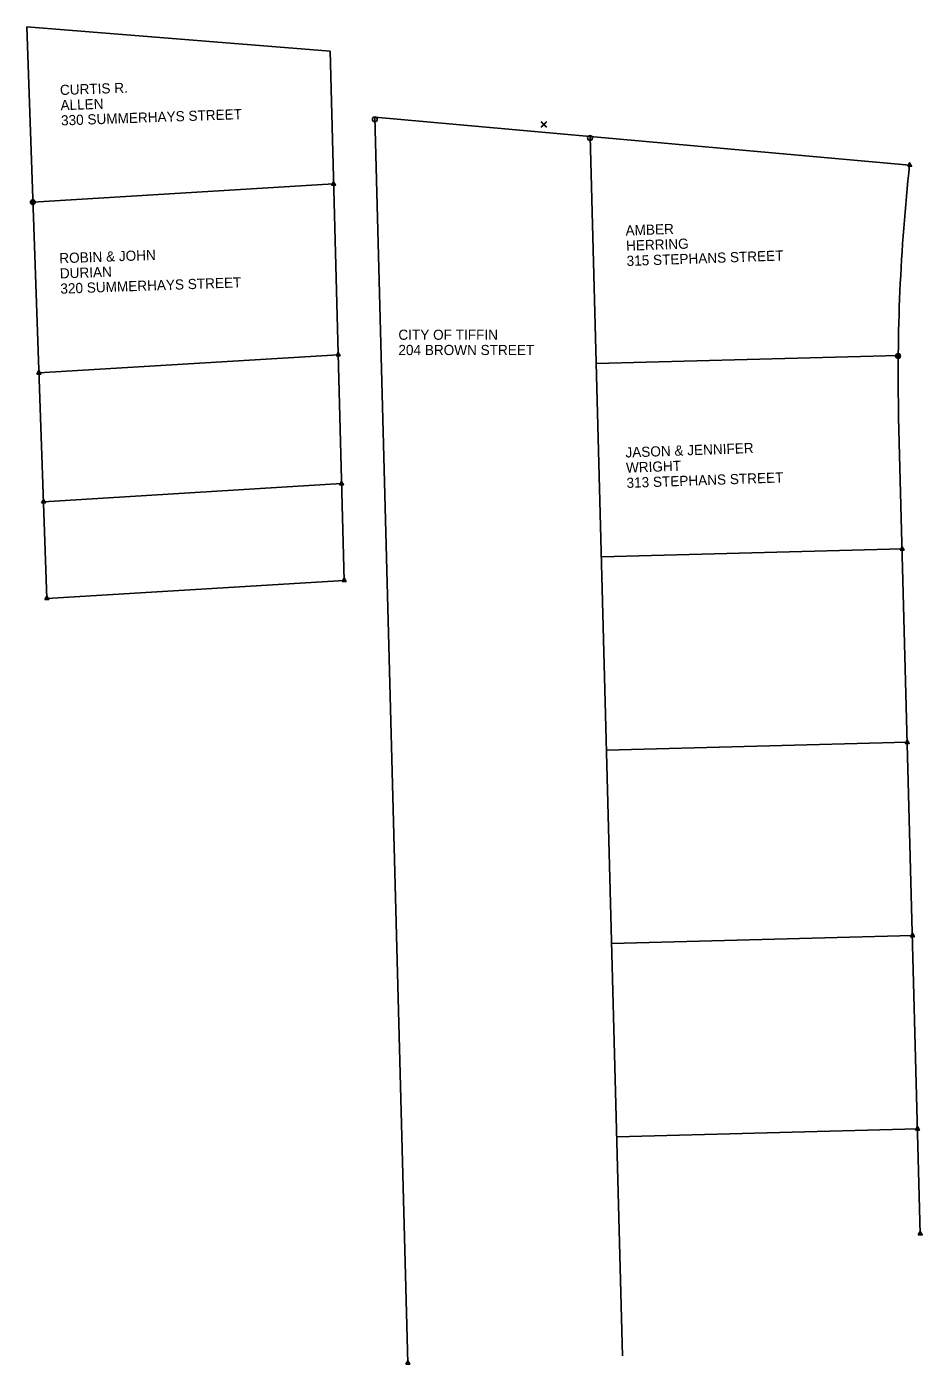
# Model space of a CAD drawing. Extents: x 20500076 to 20505422, y 7951999 to 7957351.
# Drawn here: x 20501309 to 20501726, y 7953265 to 7953888 of the extents above; entities that cross this region are included whole.
import ezdxf

# ---------------------------------------------------------------- set-up
doc = ezdxf.new("R2010")
doc.units = 0
for name, color, linetype in [('ControlPoints', 7, 'Continuous'), ('DisROW Existing', 7, 'Continuous'), ('DisROW Property Lines', 7, 'Continuous'), ('SurControl', 7, 'Continuous'), ('SurSectionCorner', 7, 'Continuous'), ('Text', 7, 'Continuous')]:
    doc.layers.add(name, color=color, linetype=linetype)

msp = doc.modelspace()

# ---------------------------------------------------------------- linework, layer by layer
at = {"layer": 'ControlPoints'}
msp.add_lwpolyline([(20501551.02, 7953843.51), (20501550.89, 7953843.64), (20501549.82, 7953842.53), (20501548.75, 7953843.64), (20501548.62, 7953843.51), (20501549.7, 7953842.4), (20501548.62, 7953841.29), (20501548.75, 7953841.16), (20501549.82, 7953842.27), (20501550.89, 7953841.16), (20501551.02, 7953841.29), (20501549.94, 7953842.4)], close=True, dxfattribs=at)
at = {"layer": 'DisROW Existing'}
for p, q in [((20501318.46, 7953621.8), (20501309.14, 7953887.86)), ((20501450.32, 7953876.56), (20501309.14, 7953887.86)), ((20501450.32, 7953876.56), (20501456.84, 7953630.2)), ((20501471.14, 7953845.77), (20501486.5, 7953265.88)), ((20501720.05, 7953823.49), (20501471.14, 7953845.77)), ((20501714.93, 7953705.96), (20501724.99, 7953326.1))]:
    msp.add_line(p, q, dxfattribs=at)
msp.add_arc((20502596.41, 7953726.45), 881.72, 173.68119, 181.33139, dxfattribs=at)
at = {"layer": 'DisROW Property Lines'}
for p, q in [((20501571.41, 7953836.8), (20501586.45, 7953269.21)), ((20501311.99, 7953806.19), (20501451.96, 7953814.69)), ((20501314.78, 7953726.77), (20501454.06, 7953735.22)), ((20501574.21, 7953731.06), (20501714.68, 7953734.78)), ((20501316.88, 7953666.79), (20501455.65, 7953675.21)), ((20501576.6, 7953641.09), (20501716.55, 7953644.8)), ((20501318.46, 7953621.8), (20501456.84, 7953630.2)), ((20501578.98, 7953551.12), (20501718.93, 7953554.83)), ((20501581.36, 7953461.15), (20501721.32, 7953464.86)), ((20501583.74, 7953371.19), (20501723.7, 7953374.89))]:
    msp.add_line(p, q, dxfattribs=at)
at = {"layer": 'SurControl'}
for centre in [(20501471.16, 7953844.78), (20501571.28, 7953836.09), (20501311.95, 7953806.22), (20501311.98, 7953806.19), (20501714.65, 7953734.63)]:
    msp.add_circle(centre, 1.12, dxfattribs=at)
at = {"layer": 'SurSectionCorner'}
for points in [[(20501719.13, 7953822.96), (20501720.96, 7953822.96), (20501720.05, 7953824.55)], [(20501451.04, 7953814.16), (20501452.87, 7953814.16), (20501451.96, 7953815.74)], [(20501311.09, 7953805.66), (20501312.92, 7953805.66), (20501312, 7953807.25)], [(20501453.15, 7953734.7), (20501454.97, 7953734.7), (20501454.06, 7953736.28)], [(20501713.82, 7953734.25), (20501715.65, 7953734.25), (20501714.73, 7953735.84)], [(20501313.87, 7953726.24), (20501315.7, 7953726.24), (20501314.78, 7953727.83)], [(20501454.74, 7953674.68), (20501456.56, 7953674.68), (20501455.65, 7953676.27)], [(20501315.97, 7953666.26), (20501317.8, 7953666.26), (20501316.88, 7953667.84)], [(20501715.64, 7953644.27), (20501717.46, 7953644.27), (20501716.55, 7953645.85)], [(20501455.93, 7953629.67), (20501457.76, 7953629.67), (20501456.84, 7953631.26)], [(20501317.54, 7953621.27), (20501319.37, 7953621.27), (20501318.46, 7953622.86)], [(20501718.02, 7953554.3), (20501719.85, 7953554.3), (20501718.93, 7953555.89)], [(20501720.4, 7953464.33), (20501722.23, 7953464.33), (20501721.32, 7953465.92)], [(20501722.78, 7953374.37), (20501724.61, 7953374.37), (20501723.7, 7953375.95)], [(20501724.08, 7953325.57), (20501725.91, 7953325.57), (20501724.99, 7953327.15)], [(20501485.59, 7953265.36), (20501487.42, 7953265.36), (20501486.5, 7953266.94)]]:
    msp.add_lwpolyline(points, close=True, dxfattribs=at)

# ---------------------------------------------------------------- texts
at = {"layer": 'Text'}
for s, height, p in [('CURTIS R.', 4.724, (20501324.68, 7953856.06)), ('ALLEN', 4.724, (20501324.93, 7953848.98)), ('330 SUMMERHAYS STREET', 4.7244, (20501325.18, 7953841.9)), ('AMBER', 4.724, (20501587.9, 7953790.67)), ('ROBIN & JOHN', 4.7244, (20501324.37, 7953777.76)), ('HERRING', 4.724, (20501588.15, 7953783.59)), ('315 STEPHANS STREET', 4.7244, (20501588.4, 7953776.5)), ('DURIAN', 4.724, (20501324.62, 7953770.68)), ('320 SUMMERHAYS STREET', 4.7244, (20501324.87, 7953763.6)), ('JASON & JENNIFER', 4.7244, (20501587.85, 7953687.37)), ('WRIGHT', 4.724, (20501588.11, 7953680.29)), ('313 STEPHANS STREET', 4.7244, (20501588.36, 7953673.21))]:
    msp.add_text(s, height=height, rotation=2.02478, dxfattribs=at).set_placement(p)
for s, p in [('CITY OF TIFFIN', (20501482.11, 7953742.15)), ('204 BROWN STREET', (20501482.11, 7953735.06))]:
    msp.add_text(s, height=4.7244, dxfattribs=at).set_placement(p)

doc.saveas('drawing.dxf')
